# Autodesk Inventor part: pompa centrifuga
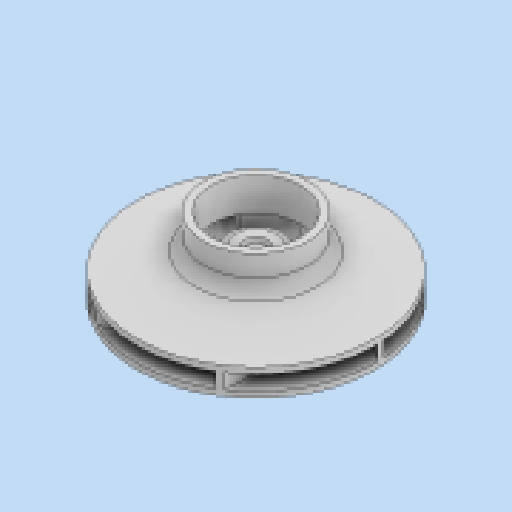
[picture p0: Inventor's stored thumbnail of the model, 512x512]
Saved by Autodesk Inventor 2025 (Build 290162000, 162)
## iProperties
Created: 2024-03
Part Number: pompa centrifuga
Material: Plastica ABS
Document SubType Name: Modeling
Designer: Ryzen5700u
Density: 1.06 g/cm^3
Appearance: Liscia - Giallo
Author: Ryzen5700u
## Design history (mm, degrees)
revolve "Rivoluzione1" stored, may be unused: angle "d7" = 360 deg
sketch "Schizzo2"
  geometry: L1 (-80, 22)-(80, 22) reference; L2 (-18, 50)-(18, 50) reference; L3 (18, 50)-(18, 22); A1 r 103.498 centre (80, 125.498) between (18, 42.626) and (80, 22); 1 further point
  constraints: 2 end point, 2 point on circle, 2 point on line, 1 centre point, 1 perpendicular, 1 tangent
feature "SupEstrusione1" sketch "Schizzo2" dims "d9" = 100, "d10" = 0
sketch "Schizzo4"
  geometry: A1 r 64.158 centre (-4.683, -60.015) between (59.177, -53.834) and (18, 0); 3 further points
  constraints: 2 point on circle, 1 centre point, 1 horizontal alignment, 3 other
feature "SupEstrusione2" sketch "Schizzo4" dims "d15" = 100, "d16" = 0
sketch "Schizzo10" dims "d78" = 60
  geometry: L1 (0, 0)-(20, 0); L2 (0, 0)-(0, 30); C1 r 45 at (0, 0) reference; A1 r 80 centre (0, 0) between (79.982, 1.684) and (39.562, -69.533) reference; A2 r 127.117 centre (0, -97.117) between (79.982, 1.684) and (0, 30); A3 r 130.117 centre (0, -97.117) between (79.8, 5.657) and (0, 33); A4 r 1.5 centre (0, 31.5) between (0, 33) and (0, 30); 2 further points
  constraints: 9 point on circle, 4 end point, 3 centre point, 2 tangent, 1 coincident, 1 horizontal, 1 vertical, 1 vertical alignment, 2 other
  dimensions: "d76" = 3 radial gap between concentric circles of A2 A3
extrude "Estrusione3" join sketch "Schizzo10" stored distance "d29" = 10; taper "d30" = 0 deg
sketch "Schizzo11"
  geometry: L1 (-18, 50)-(18, 50) reference; L2 (-80, 22)-(80, 22) reference; L3 (12, 5)-(12, 50) reference; L4 (12, 50)-(25, 50); L5 (80, 22)-(80, 32); L6 (25, 50)-(83.214, 50); L7 (83.214, 50)-(83.214, 22); L8 (83.214, 22)-(80, 22); L9 (0, -40.399)-(0, 242.395) reference; L10 (0, 50)-(0, 29.098) reference; L11 (0, 50)-(25, 50); A1 r 170 centre (104.605, 200.21) between (25, 50) and (80, 32); 5 further points
  constraints: 12 end point, 2 perpendicular, 2 point on circle, 1 centre point, 1 collinear, 1 horizontal, 1 point on line, 1 vertical
  dimensions: "d32" = 10 distance of L2.end L5.end; "d79" = 25 distance of L10.start L4.end
revolve "Rivoluzione3" sketch "Schizzo11" stored, may be unused: angle "d33" = 360 deg
revolve "Rivoluzione4" stored, may be unused: angle "d50" = 360 deg
pattern_circular "Serie circolare3" dims "d55" = 360 deg
fillet "Raccordo5" dims "d51" = 15
fillet "Raccordo6" dims "d60" = 2
sketch "Schizzo13"
  geometry: L1 (45, 18)-(45, 0) reference; L2 (-80, 18)-(80, 18) reference; L3 (0, 0)-(0, 91); C1 r 1.5 at (45, 16.5)
  constraints: 2 end point, 1 centre point, 1 point on line, 1 tangent, 1 vertical
  dimensions: "d61" = 3 diameter of C1
revolve "Rivoluzione5" sketch "Schizzo13" stored, may be unused: angle "d62" = 90 deg
sketch "Schizzo14"
  geometry: L1 (0, 0)-(-66.662, -66.662); L2 (0, 0)-(94.274, 0); 1 further point
  constraints: 4 end point, 1 equal length, 1 horizontal, 1 point on line
  dimensions: "d74" = 135 deg angle of L1 L2; "d75" = 25 distance of L1.start point (-17.678, -17.678)
hole "Foro1" sketch "Schizzo14" at (-17.678, -17.678) diameter "d64" = 4.3; stored, may be unused: countersink angle "d68" = 90 deg, drill point angle "d70" = 0 deg; dims "d65" = 48, "d66" = 20, "d67" = 2, "d69" = 61.1
pattern_circular "Serie circolare4" dims angle "d72" = 360 deg
sketch "Schizzo15"
  geometry: L1 (80, 32)-(80, 36.044); L2 (0, 0)-(0, 70.03); L3 (30, 47.455)-(30, 70); L4 (35, 49.508)-(35, 70); L5 (35, 70)-(30, 70); L6 (-12, 50)-(12, 50) reference; A1 r 170 centre (104.605, 200.21) between (25, 50) and (80, 32) reference; A2 r 166 centre (104.605, 200.21) between (30, 51.919) and (80, 36.044); 1 further point
  constraints: 10 end point, 4 point on circle, 3 vertical, 1 centre point, 1 horizontal, 1 parallel, 1 point on line
  dimensions: "d81" = 4 radial gap between concentric circles of A1 A2; "d83" = 5 distance between parallel lines of L3 L4; "d84" = 30 distance between parallel lines of L2 L3; "d85" = 20 distance between parallel lines of L5 L6
revolve "Rivoluzione6" sketch "Schizzo15" stored, may be unused: angle "d82" = 360 deg
fillet "Raccordo7" dims "d86" = 10
sketch "Schizzo16"
  geometry: C1 r 52.305 at (0, 0); 1 further point
  constraints: 1 centre point, 1 coincident
extrude "Estrusione4" cut sketch "Schizzo16" stored distance "d87" = 10; taper "d88" = 0 deg
node "Piano di lavoro4"
sketch "Schizzo17"
  geometry: A1 r 2.15 centre (-17.678, 17.678) between (-19.198, 19.198) and (-17.225, 15.576) reference; 4 further points
  constraints: 1 point on circle, 5 other
hole "Foro2" sketch "Schizzo17" at (-17.678, 17.678) diameter "d90" = 4.3; stored, may be unused: countersink angle "d94" = 90 deg, drill point angle "d96" = 0 deg; dims "d91" = 6, "d92" = 8, "d93" = 24, "d95" = 61.1
pattern_circular "Serie circolare5" dims angle "d98" = 360 deg
sketch "Schizzo18"
  geometry: C1 r 18 at (0, 0) reference; C2 r 10 at (0, 0); C3 r 12 at (0, 0) reference; 1 further point
  constraints: 1 centre point, 1 coincident
  dimensions: "d100" = 20 diameter of C2
extrude "Estrusione5" join sketch "Schizzo18" distance "d101" = 10; taper "d102" = 0 deg
fillet "Raccordo8" dims "d103" = 5
sketch "Schizzo19"
  geometry: C1 r 13.807 at (0, 0) reference; 2 further points
  constraints: 1 coincident
hole "Foro3" sketch "Schizzo19" at (0, 0) diameter "d104" = 8.4; stored, may be unused: countersink angle "d108" = 90 deg, drill point angle "d110" = 0 deg; dims "d105" = 6, "d106" = 15, "d107" = 4, "d109" = 61.1
sketch "Schizzo20"
  geometry: C1 r 12 at (0, 0) reference; C2 r 10 at (0, 0) reference; 1 further point
extrude "Estrusione6" join sketch "Schizzo20" stored distance "d111" = 10; taper "d112" = 0 deg
node "Solido1"
sketch "Schizzo1"
  geometry: L1 (0, 0)-(80, 0); L2 (80, 18)-(80, 22); L3 (0, 0)-(0, 50); L4 (0, 50)-(18, 50); L5 (12, 50)-(12, 0); L6 (12, 5)-(18, 5); L7 (18, 5)-(18, 15); L8 (18, 15)-(35, 15); L9 (50, 15)-(50, 15); L10 (45, 18)-(80, 18); L11 (45, 18)-(45, 0); L12 (45, 0)-(35, 0); L13 (35, 0)-(35, 15); A1 r 120 centre (96.365, 140.879) between (18, 50) and (80, 22); A2 r 30 centre (47.826, 53.228) between (18, 50) and (45.295, 23.335); A3 r 377.526 centre (77.14, 399.515) between (45.295, 23.335) and (80, 22); 1 further point
  constraints: 26 end point, 8 perpendicular, 6 point on circle, 4 point on line, 3 centre point, 1 horizontal, 1 parallel, 1 tangent, 1 vertical
  dimensions: "d0" = 80 distance of L1.start L1.end; "d1" = 22 distance of L1.end L2.end; "d3" = 50 distance of L1.start L3.end; "d4" = 18 distance of L3.end L4.end; "d6" = 12 distance between parallel lines of L3 L5; "d41" = 18 distance between parallel lines of L3 L7; "d42" = 5 distance from line of L1.start L6; "d43" = 15 distance from line of L1.start L8; "d45" = 18 distance from line of L1.end L10; "d58" = 35 distance from line of L1.start L13; "d59" = 45 distance from line of L1.start L11; "d80" = 30 radius of A2
node "Superf1"
node "Superf2"
sketch "Schizzo12"
  geometry: L1 (0, 54)-(0, 83.677); L2 (0, 70)-(-24.994, 70); 9 further points
  constraints: 4 end point, 1 perpendicular, 1 vertical, 7 other
  dimensions: "d49" = 16 dimension on L1.start
node "Riferimento1"
other parameters: "d89" = -9
